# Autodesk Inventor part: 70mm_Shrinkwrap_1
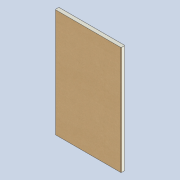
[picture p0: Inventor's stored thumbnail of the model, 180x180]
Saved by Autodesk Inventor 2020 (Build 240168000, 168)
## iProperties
Created: 2020-11
Part Number: 70mm_Shrinkwrap_1
Material: Generic
Document SubType Name: Modeling
Designer: Yolande
Density: 1 g/cm^3
Appearance: Default
Author: Yolande
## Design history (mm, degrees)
derived "70mm.iam"
body "Solid1"
node "Lambdaboard 70mm Kraft.ipt:1" dims "d0" = 10
